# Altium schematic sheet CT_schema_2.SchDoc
size 283 x 147 mm
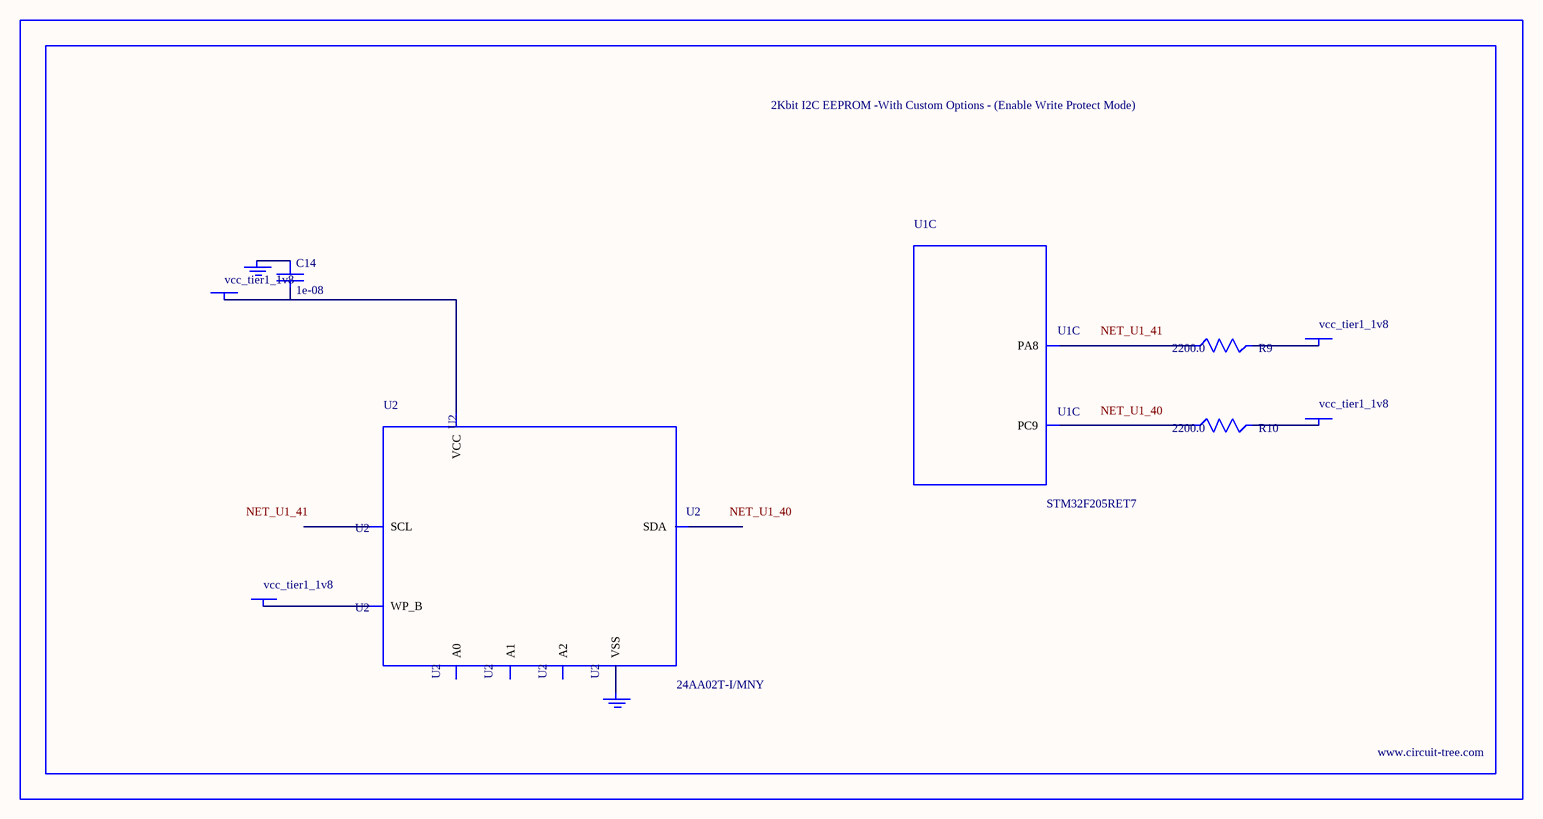
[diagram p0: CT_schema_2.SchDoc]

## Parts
BORDER1  (no value)
C14  1e-08  [C0402]
GND_INSTANCE_1_0  (no value)
GND_INSTANCE_1_1  (no value)
POWER_INSTANCE_1_0  vcc_tier1_1v8
POWER_INSTANCE_1_1  vcc_tier1_1v8
POWER_INSTANCE_1_2  vcc_tier1_1v8
POWER_INSTANCE_1_3  vcc_tier1_1v8
R9  2200.0  [R0603]
R10  2200.0  [R0603]
U1  STM32F205RET7  [LQFP64]  (part C of 5)
U2  24AA02T-I/MNY  [TDFN-8/6MM]

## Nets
NetC14_1: C14.1 GND_INSTANCE_1_0.0(GND)
NetC14_2: C14.2 POWER_INSTANCE_1_1.0(PWR) U2.8(VCC)
NetGND_INSTANCE_1_1_0: GND_INSTANCE_1_1.0(GND) U2.4(VSS)
NetPOWER_INSTANCE_1_0_0: POWER_INSTANCE_1_0.0(PWR) U2.7(WP_B)
NetPOWER_INSTANCE_1_2_0: POWER_INSTANCE_1_2.0(PWR) R10.2
NetPOWER_INSTANCE_1_3_0: POWER_INSTANCE_1_3.0(PWR) R9.2
NetR9_1: R9.1 U1.41(PA8)
NetR10_1: R10.1 U1.40(PC9)

Not connected (* = marked no-connect by the designer): U2 1(A0) 2(A1) 3(A2) 5(SDA) 6(SCL)

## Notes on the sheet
- Labels drawn without touching a wire or pin: NET_U1_40, NET_U1_41

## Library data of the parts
BORDER1 = BORDER_PAGE1
C14 = C0402C103K3RAC
GND_INSTANCE_1_0 GND_INSTANCE_1_1 = GND
POWER_INSTANCE_1_0-POWER_INSTANCE_1_3 = PWR
R9 R10 = RC0603JR-072K2L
